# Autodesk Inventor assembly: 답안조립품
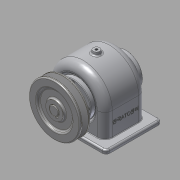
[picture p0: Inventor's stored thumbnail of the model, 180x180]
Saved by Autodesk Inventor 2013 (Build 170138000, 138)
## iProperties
Created: 2015-09
Part Number: 답안조립품
Document SubType Name: Assembly
Designer: dgall
Author: dgall
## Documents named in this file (14)
- C:\Users\dgall\Desktop\450907V1008\답안조립품.iam
- C:\Users\dgall\Desktop\450907V1008\본체.ipt
- C:\Users\dgall\Desktop\450907V1008\볼트 M3 x 8.ipt
- C:\Users\dgall\Desktop\450907V1008\볼트 M3 x 10.ipt
- C:\Users\dgall\Desktop\450907V1008\스퍼기어.ipt
- C:\Users\dgall\Desktop\450907V1008\앞커버.ipt
- C:\Users\dgall\Desktop\450907V1008\오일 실 17 32 8.ipt
- C:\Users\dgall\Desktop\450907V1008\축.ipt
- C:\Users\dgall\Desktop\450907V1008\키 - 5 x 5 x 18.ipt
- C:\Users\dgall\Desktop\450907V1008\키 - 6 x 6 x 22.ipt
- C:\Users\dgall\Desktop\450907V1008\V-벨트풀리.ipt
- C:\Users\dgall\Desktop\450907V1008\뒤커버.ipt
- C:\Users\dgall\Desktop\450907V1008\멈춤나사 - M4x10.ipt
- C:\Users\dgall\Desktop\450907V1008\베어링 6203.ipt
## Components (9 placed, 3 different names)
1. ISO 4762 M3 x 8:1
2. ISO 4762 M3 x 10:1
3. V-벨트풀리:1
4. ISO 4762 M3 x 8:2
5. ISO 4762 M3 x 8:3
6. ISO 4762 M3 x 10:2
7. ISO 4762 M3 x 10:3
8. ISO 4762 M3 x 10:4
9. ISO 4762 M3 x 8:4
